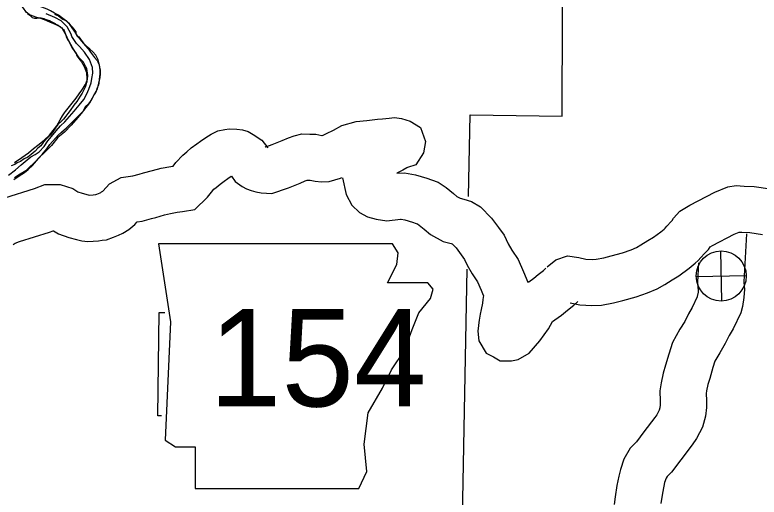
# Model space of a CAD drawing. Extents: x 1374139 to 1377472, y 1168351 to 1170484.
# Drawn here: x 1374769.01 to 1374817.41, y 1169739.38 to 1169770.73 of the extents above; entities that cross this region are included whole.
import ezdxf

# ---------------------------------------------------------------- set-up
doc = ezdxf.new("R2010")
doc.units = 0
doc.layers.add('Default', color=7, linetype='Continuous')

msp = doc.modelspace()

# ---------------------------------------------------------------- linework, layer by layer
at = {"layer": 'Default'}
for p, q in [((1374814.986, 1169752.131), (1374814.911, 1169755.386)), ((1374813.321, 1169753.721), (1374816.576, 1169753.796))]:
    msp.add_line(p, q, dxfattribs=at)
for points in [[(1374804.595, 1169764.152), (1374804.673, 1169783.979), (1374811.369, 1169784.017), (1374811.293, 1169790.603), (1374811.141, 1169803.756)], [(1374771.844, 1169770.706), (1374771.59, 1169770.85), (1374771.326, 1169771.003), (1374771.113, 1169771.107), (1374770.76, 1169771.228), (1374770.488, 1169771.311), (1374770.315, 1169771.407), (1374770.244, 1169771.465), (1374770.17, 1169771.604), (1374770.085, 1169771.792), (1374770.072, 1169771.902)], [(1374771.691, 1169770.081), (1374771.277, 1169770.26), (1374770.933, 1169770.412), (1374770.63, 1169770.524), (1374770.439, 1169770.559), (1374770.146, 1169770.671), (1374769.943, 1169770.766), (1374769.759, 1169770.912), (1374769.676, 1169771.02), (1374769.614, 1169771.098), (1374769.52, 1169771.256), (1374769.446, 1169771.394), (1374769.423, 1169771.494)], [(1374768.601, 1169760.314), (1374769.052, 1169760.666), (1374769.433, 1169760.987), (1374769.814, 1169761.307), (1374770.058, 1169761.494), (1374770.334, 1169761.661), (1374770.589, 1169761.838), (1374770.91, 1169762.167), (1374771.159, 1169762.534), (1374771.391, 1169762.831), (1374771.691, 1169763.189), (1374771.982, 1169763.508), (1374772.255, 1169763.785), (1374772.565, 1169764.134), (1374772.876, 1169764.463), (1374773.195, 1169764.862), (1374773.495, 1169765.23), (1374773.684, 1169765.596), (1374773.826, 1169765.91), (1374773.974, 1169766.324), (1374774.017, 1169766.586), (1374774.077, 1169766.948), (1374774.057, 1169767.308), (1374773.873, 1169767.824), (1374773.55, 1169768.317), (1374773.21, 1169768.668), (1374773.014, 1169768.874), (1374772.722, 1169769.327), (1374772.668, 1169769.485), (1374772.405, 1169769.949), (1374772.024, 1169770.34), (1374771.609, 1169770.55), (1374771.042, 1169770.795)], [(1374768.939, 1169760.032), (1374769.283, 1169760.261), (1374769.636, 1169760.491), (1374769.871, 1169760.678), (1374770.164, 1169760.946), (1374770.426, 1169761.233), (1374770.57, 1169761.417), (1374770.794, 1169761.663), (1374771.093, 1169762.032), (1374771.296, 1169762.298), (1374771.47, 1169762.502), (1374771.654, 1169762.718), (1374771.839, 1169762.913), (1374772.053, 1169763.109), (1374772.366, 1169763.387), (1374772.648, 1169763.665), (1374772.94, 1169763.943), (1374773.231, 1169764.261), (1374773.494, 1169764.519), (1374773.89, 1169765.02), (1374774.061, 1169765.345), (1374774.223, 1169765.63), (1374774.395, 1169765.925), (1374774.555, 1169766.65), (1374774.588, 1169766.891), (1374774.572, 1169767.141), (1374774.478, 1169767.63), (1374774.423, 1169767.809), (1374774.285, 1169768.106), (1374774.079, 1169768.33), (1374773.894, 1169768.506), (1374773.741, 1169768.622), (1374773.515, 1169768.847), (1374773.504, 1169768.866), (1374773.256, 1169769.16), (1374773.092, 1169769.326), (1374772.882, 1169769.681), (1374772.746, 1169769.888), (1374772.58, 1169770.114), (1374772.395, 1169770.3), (1374772.14, 1169770.503), (1374771.844, 1169770.706)], [(1374771.6, 1169770.786), (1374771.843, 1169770.662), (1374771.955, 1169770.584), (1374772.129, 1169770.459), (1374772.21, 1169770.411), (1374772.341, 1169770.364), (1374772.495, 1169770.218), (1374772.618, 1169770.091), (1374772.711, 1169769.983), (1374772.804, 1169769.885), (1374772.856, 1169769.796), (1374772.971, 1169769.639), (1374772.982, 1169769.589), (1374772.985, 1169769.489), (1374773.058, 1169769.361), (1374773.18, 1169769.304), (1374773.574, 1169768.763), (1374773.801, 1169768.498), (1374773.937, 1169768.302), (1374774.071, 1169768.135), (1374774.186, 1169767.967), (1374774.371, 1169767.772), (1374774.413, 1169767.673), (1374774.489, 1169767.474), (1374774.523, 1169767.325), (1374774.539, 1169767.105), (1374774.534, 1169766.904), (1374774.504, 1169766.533), (1374774.471, 1169766.302), (1374774.454, 1169766.191), (1374774.417, 1169766.08), (1374774.34, 1169765.938), (1374774.313, 1169765.847), (1374774.277, 1169765.696), (1374774.21, 1169765.584), (1374774.152, 1169765.502), (1374774.115, 1169765.421), (1374774, 1169765.228), (1374773.913, 1169765.095), (1374773.797, 1169764.952), (1374773.593, 1169764.756), (1374773.441, 1169764.452), (1374773.112, 1169764.062), (1374772.665, 1169763.57), (1374772.248, 1169763.108), (1374771.817, 1169762.766), (1374771.391, 1169762.244), (1374770.905, 1169761.751), (1374770.632, 1169761.493), (1374770.262, 1169761.123), (1374769.951, 1169760.804), (1374769.717, 1169760.598), (1374769.255, 1169760.306), (1374768.98, 1169760.128)], [(1374769.839, 1169770.83), (1374769.982, 1169770.714), (1374770.074, 1169770.636), (1374770.147, 1169770.558), (1374770.287, 1169770.521), (1374770.377, 1169770.523), (1374770.437, 1169770.525), (1374770.587, 1169770.549), (1374770.717, 1169770.532), (1374770.898, 1169770.487), (1374770.989, 1169770.459), (1374771.12, 1169770.412), (1374771.272, 1169770.356), (1374771.383, 1169770.309), (1374771.545, 1169770.223), (1374771.626, 1169770.175), (1374771.687, 1169770.137), (1374771.82, 1169770.06), (1374771.881, 1169770.011), (1374771.982, 1169769.964), (1374772.044, 1169769.895), (1374772.064, 1169769.886), (1374772.106, 1169769.827), (1374772.177, 1169769.779), (1374772.219, 1169769.72), (1374772.272, 1169769.581), (1374772.305, 1169769.471), (1374772.36, 1169769.303), (1374772.423, 1169769.174), (1374772.476, 1169769.075), (1374772.497, 1169769.036), (1374772.76, 1169768.552), (1374772.999, 1169768.227), (1374773.043, 1169768.078), (1374773.178, 1169767.901), (1374773.343, 1169767.685), (1374773.522, 1169767.369), (1374773.555, 1169767.27), (1374773.651, 1169767.032), (1374773.663, 1169766.942), (1374773.676, 1169766.842), (1374773.69, 1169766.712), (1374773.689, 1169766.382), (1374773.652, 1169766.26), (1374773.597, 1169766.069), (1374773.569, 1169765.998), (1374773.484, 1169765.815), (1374773.389, 1169765.642), (1374773.254, 1169765.439), (1374773.034, 1169765.092), (1374772.84, 1169764.857), (1374772.609, 1169764.52), (1374772.455, 1169764.316), (1374772.329, 1169764.152), (1374772.175, 1169763.958)], [(1374768.989, 1169761.125), (1374769.459, 1169761.468), (1374769.891, 1169761.77), (1374770.223, 1169762.039), (1374770.517, 1169762.257), (1374770.908, 1169762.588), (1374771.269, 1169762.918), (1374771.732, 1169763.521), (1374771.857, 1169763.715), (1374771.961, 1169763.918), (1374772.114, 1169764.162), (1374772.249, 1169764.356), (1374772.316, 1169764.448), (1374772.49, 1169764.673), (1374772.731, 1169765), (1374772.993, 1169765.307), (1374773.194, 1169765.603), (1374773.358, 1169765.827), (1374773.454, 1169765.96), (1374773.589, 1169766.174), (1374773.655, 1169766.316), (1374773.728, 1169766.558), (1374773.751, 1169766.799), (1374773.737, 1169766.949), (1374773.689, 1169767.248), (1374773.636, 1169767.357), (1374773.468, 1169767.663), (1374773.2, 1169767.937), (1374772.93, 1169768.32), (1374772.762, 1169768.606), (1374772.53, 1169769.041), (1374772.414, 1169769.258), (1374772.286, 1169769.536), (1374772.139, 1169769.812), (1374771.965, 1169769.958), (1374771.691, 1169770.081)], [(1374798.521, 1169758.921), (1374798.625, 1169764.226), (1374804.595, 1169764.152)], [(1374772.175, 1169763.958), (1374772.048, 1169763.824), (1374771.805, 1169763.598), (1374771.709, 1169763.455), (1374771.651, 1169763.373), (1374771.574, 1169763.251), (1374771.487, 1169763.139), (1374771.303, 1169762.913), (1374771.119, 1169762.718), (1374770.847, 1169762.431), (1374770.692, 1169762.226), (1374770.507, 1169762.061), (1374770.332, 1169761.876), (1374770.078, 1169761.649), (1374769.863, 1169761.483), (1374769.615, 1169761.377), (1374769.37, 1169761.2), (1374769.163, 1169761.115), (1374769.016, 1169761.011), (1374768.778, 1169760.914)], [(1374785.28, 1169762.173), (1374785.321, 1169762.162), (1374785.333, 1169762.16), (1374785.743, 1169762.302), (1374786.406, 1169762.571), (1374786.815, 1169762.746), (1374787.184, 1169762.875), (1374787.674, 1169762.991), (1374788.187, 1169762.987), (1374788.586, 1169762.967), (1374788.983, 1169762.889), (1374789.004, 1169762.887), (1374789.058, 1169762.903), (1374789.27, 1169763.013), (1374789.743, 1169763.246), (1374790.277, 1169763.545), (1374791.214, 1169763.81), (1374791.904, 1169763.864), (1374792.586, 1169763.942), (1374792.931, 1169763.972), (1374793.357, 1169764.011), (1374793.709, 1169764.057), (1374794.159, 1169764), (1374794.432, 1169763.917), (1374794.715, 1169763.831), (1374795.381, 1169763.411), (1374795.713, 1169762.495), (1374795.588, 1169761.761), (1374795.098, 1169760.98), (1374794.553, 1169760.808), (1374794.499, 1169760.787), (1374794.233, 1169760.628), (1374793.852, 1169760.443), (1374794.357, 1169760.456), (1374795.074, 1169760.326), (1374795.805, 1169760.107), (1374796.103, 1169760.001), (1374796.533, 1169759.848), (1374797.07, 1169759.499), (1374797.546, 1169759.117), (1374797.763, 1169758.931), (1374797.971, 1169758.818), (1374798.205, 1169758.757), (1374798.701, 1169758.605), (1374799.294, 1169758.261), (1374800.012, 1169757.523), (1374800.453, 1169756.903), (1374800.828, 1169756.401), (1374801.095, 1169755.854), (1374801.322, 1169755.444), (1374801.733, 1169754.82), (1374802.085, 1169754.037), (1374802.38, 1169753.351), (1374802.428, 1169753.385), (1374802.769, 1169753.611), (1374803.047, 1169753.845), (1374803.381, 1169754.115), (1374803.541, 1169754.268)], [(1374768.367, 1169758.848), (1374770.296, 1169759.446), (1374770.961, 1169759.698), (1374771.949, 1169759.703), (1374772.786, 1169759.435), (1374773.114, 1169759.231), (1374773.393, 1169759.141), (1374773.777, 1169759.035), (1374773.865, 1169759.013), (1374774.11, 1169759.029), (1374774.273, 1169759.057), (1374774.346, 1169759.085), (1374774.568, 1169759.171), (1374774.609, 1169759.19), (1374774.656, 1169759.218), (1374774.727, 1169759.28), (1374775.16, 1169759.738), (1374775.927, 1169760.16), (1374776.689, 1169760.272), (1374777.104, 1169760.382), (1374777.369, 1169760.456), (1374777.969, 1169760.625), (1374778.529, 1169760.77), (1374779.148, 1169760.87), (1374779.297, 1169760.887), (1374779.474, 1169761.125), (1374779.929, 1169761.621), (1374780.19, 1169761.819), (1374780.485, 1169762.086), (1374780.856, 1169762.345), (1374781.087, 1169762.518), (1374781.438, 1169762.766), (1374781.787, 1169762.98), (1374782.216, 1169763.198), (1374782.67, 1169763.286), (1374782.956, 1169763.314), (1374783.445, 1169763.312), (1374783.812, 1169763.265), (1374784.185, 1169763.14), (1374784.515, 1169762.963), (1374785.07, 1169762.577), (1374785.466, 1169762.083)], [(1374768.899, 1169755.805), (1374769.031, 1169755.9), (1374769.315, 1169756.002), (1374771.272, 1169756.608), (1374771.504, 1169756.696), (1374771.519, 1169756.691), (1374771.841, 1169756.491), (1374772.531, 1169756.266), (1374773.013, 1169756.134), (1374773.375, 1169756.043), (1374773.75, 1169755.999), (1374774.462, 1169756.046), (1374774.698, 1169756.086), (1374774.972, 1169756.115), (1374775.418, 1169756.283), (1374775.75, 1169756.412), (1374776.025, 1169756.541), (1374776.43, 1169756.785), (1374776.808, 1169757.115), (1374776.965, 1169757.281), (1374777.292, 1169757.329), (1374777.889, 1169757.486), (1374778.18, 1169757.568), (1374778.751, 1169757.729), (1374779.144, 1169757.83), (1374779.559, 1169757.897), (1374779.918, 1169757.939), (1374780.717, 1169758.089), (1374781.549, 1169758.887), (1374781.79, 1169759.212), (1374781.956, 1169759.393), (1374782.106, 1169759.507), (1374782.357, 1169759.734), (1374782.614, 1169759.913), (1374782.854, 1169760.093), (1374783.085, 1169760.256), (1374783.122, 1169760.209)], [(1374783.092, 1169760.249), (1374783.349, 1169759.904), (1374783.785, 1169759.582), (1374784.079, 1169759.416), (1374784.39, 1169759.306), (1374784.691, 1169759.225), (1374785.04, 1169759.168), (1374785.716, 1169759.118), (1374786.798, 1169759.493), (1374787.559, 1169759.801), (1374787.9, 1169759.947), (1374788.017, 1169759.988), (1374788.1, 1169759.988), (1374788.221, 1169759.981), (1374788.548, 1169759.918), (1374788.952, 1169759.878), (1374789.453, 1169759.891), (1374790.187, 1169760.109), (1374790.278, 1169760.156)], [(1374790.31, 1169760.146), (1374790.567, 1169759.051), (1374790.927, 1169758.355), (1374791.428, 1169757.88), (1374791.947, 1169757.596), (1374792.508, 1169757.444), (1374793.206, 1169757.343), (1374794.09, 1169757.448), (1374794.126, 1169757.449), (1374794.374, 1169757.404), (1374794.872, 1169757.255), (1374795.099, 1169757.174), (1374795.194, 1169757.14), (1374795.309, 1169757.066), (1374795.63, 1169756.808), (1374796.049, 1169756.449), (1374796.855, 1169756.009), (1374797.387, 1169755.869), (1374797.455, 1169755.849), (1374797.701, 1169755.596), (1374798.029, 1169755.135), (1374798.256, 1169754.831), (1374798.434, 1169754.468), (1374798.753, 1169753.891), (1374799.095, 1169753.372), (1374799.339, 1169752.828), (1374799.471, 1169752.521), (1374799.481, 1169752.491), (1374799.481, 1169752.49), (1374799.449, 1169752.223), (1374799.425, 1169751.999), (1374799.33, 1169751.575), (1374799.262, 1169751.282), (1374799.206, 1169750.878), (1374799.193, 1169750.731), (1374799.159, 1169750.535), (1374799.125, 1169750.18), (1374799.183, 1169749.534), (1374799.67, 1169748.732), (1374800.136, 1169748.497), (1374800.575, 1169748.233), (1374801.299, 1169748.252), (1374801.738, 1169748.326), (1374802.448, 1169748.734), (1374803.147, 1169749.547), (1374803.718, 1169750.324), (1374803.971, 1169750.799), (1374803.977, 1169750.806), (1374804.124, 1169750.91), (1374804.569, 1169751.206), (1374804.955, 1169751.53), (1374805.364, 1169751.861), (1374805.614, 1169752.1)], [(1374803.624, 1169754.342), (1374804.186, 1169754.804), (1374804.948, 1169755.065), (1374805.693, 1169754.954), (1374806.139, 1169754.861), (1374806.549, 1169754.837), (1374806.819, 1169754.851), (1374807.311, 1169754.941), (1374807.785, 1169755.06), (1374808.531, 1169755.263), (1374809.082, 1169755.457), (1374809.441, 1169755.608), (1374809.729, 1169755.773), (1374810.169, 1169756.057), (1374810.541, 1169756.279), (1374811.017, 1169756.622), (1374811.234, 1169756.807), (1374811.303, 1169756.875), (1374811.419, 1169756.997), (1374811.697, 1169757.302), (1374811.757, 1169757.361), (1374811.848, 1169757.507), (1374812.261, 1169757.968), (1374812.913, 1169758.355), (1374814.529, 1169759.214), (1374815.382, 1169759.547), (1374815.917, 1169759.642), (1374816.438, 1169759.599), (1374817.085, 1169759.583), (1374818.125, 1169759.419)], [(1374805.123, 1169752.008), (1374805.745, 1169751.878), (1374806.536, 1169751.833), (1374807.165, 1169751.864), (1374807.947, 1169752.007), (1374808.544, 1169752.157), (1374809.426, 1169752.397), (1374810.162, 1169752.657), (1374810.771, 1169752.913), (1374811.29, 1169753.21), (1374811.754, 1169753.51), (1374812.189, 1169753.769), (1374812.869, 1169754.259), (1374813.258, 1169754.59), (1374813.442, 1169754.77), (1374813.617, 1169754.955), (1374813.863, 1169755.225), (1374814.115, 1169755.474), (1374814.22, 1169755.642), (1374814.384, 1169755.74), (1374815.783, 1169756.483), (1374816.121, 1169756.615), (1374816.279, 1169756.602), (1374816.813, 1169756.589), (1374817.621, 1169756.461)], [(1374816.584, 1169756.5), (1374816.413, 1169753.378), (1374816.433, 1169753.093), (1374816.462, 1169752.907), (1374816.423, 1169752.352), (1374816.32, 1169751.765), (1374816.213, 1169751.367), (1374815.714, 1169750.321), (1374815.471, 1169749.895), (1374815.206, 1169749.359), (1374814.848, 1169748.771), (1374814.538, 1169748.228), (1374814.407, 1169747.809), (1374814.198, 1169747.1), (1374814.079, 1169746.705), (1374813.996, 1169746.303), (1374813.97, 1169746.122), (1374813.983, 1169745.668), (1374813.982, 1169745.219), (1374813.922, 1169744.635), (1374813.727, 1169743.938), (1374813.338, 1169743.192), (1374813.062, 1169742.786), (1374812.313, 1169741.816), (1374811.72, 1169741.005), (1374811.431, 1169740.723), (1374811.367, 1169740.608), (1374811.269, 1169740.334), (1374811.214, 1169740.101), (1374811.121, 1169739.631), (1374811.025, 1169738.97)], [(1374813.476, 1169754.622), (1374813.407, 1169753.351), (1374813.447, 1169752.797), (1374813.441, 1169752.715), (1374813.389, 1169752.417), (1374813.387, 1169752.411), (1374813.054, 1169751.713), (1374812.821, 1169751.305), (1374812.575, 1169750.806), (1374812.263, 1169750.295), (1374811.772, 1169749.434), (1374811.536, 1169748.681), (1374811.323, 1169747.957), (1374811.168, 1169747.443), (1374811.039, 1169746.818), (1374810.964, 1169746.295), (1374810.983, 1169745.628), (1374810.982, 1169745.376), (1374810.964, 1169745.197), (1374810.922, 1169745.046), (1374810.76, 1169744.736), (1374810.633, 1169744.55), (1374809.914, 1169743.618), (1374809.448, 1169742.98), (1374809.017, 1169742.561), (1374808.623, 1169741.843), (1374808.388, 1169741.187), (1374808.281, 1169740.735), (1374808.163, 1169740.137), (1374808.058, 1169739.411), (1374807.981, 1169738.902)], [(1374804.127, 1169719.47), (1374798.677, 1169719.513), (1374798.163, 1169737.81), (1374798.134, 1169739.222), (1374798.428, 1169754.193)], [(1374778.309, 1169744.672), (1374778.394, 1169751.385), (1374778.761, 1169751.379)], [(1374778.55, 1169744.671), (1374778.309, 1169744.672)]]:
    msp.add_lwpolyline(points, dxfattribs=at)
msp.add_lwpolyline([(1374778.364, 1169755.856), (1374779.126, 1169750.781), (1374778.787, 1169743.083), (1374779.464, 1169742.66), (1374780.733, 1169742.66), (1374780.733, 1169739.953), (1374791.391, 1169739.953), (1374791.899, 1169741.053), (1374791.729, 1169742.83), (1374791.983, 1169744.86), (1374792.914, 1169746.467), (1374793.506, 1169747.651), (1374794.352, 1169748.92), (1374794.859, 1169750.273), (1374795.282, 1169751.373), (1374796.043, 1169752.304), (1374796.213, 1169752.896), (1374795.874, 1169753.319), (1374793.252, 1169753.319), (1374793.844, 1169754.503), (1374793.929, 1169755.264), (1374793.578, 1169755.849)], close=True, dxfattribs=at)
msp.add_circle((1374814.948, 1169753.758), 1.628, dxfattribs=at)

# ---------------------------------------------------------------- texts
msp.add_text('154', height=6.336, dxfattribs=at).set_placement((1374781.638, 1169745.276))

doc.saveas('drawing.dxf')
